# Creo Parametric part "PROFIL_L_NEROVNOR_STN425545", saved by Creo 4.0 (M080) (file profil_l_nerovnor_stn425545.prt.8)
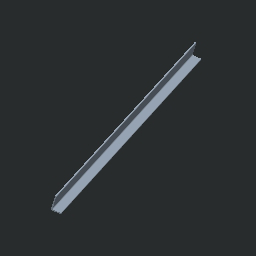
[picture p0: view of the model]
Units: millimeter Kilogram Sec (mmKs); MM, KILOGRAM, SECS
Materials in the file: OCEL_N

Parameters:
  MFG_WP_MATERIAL = "OCEL"
  NAZOV = "PROFIL_L_NEROVNOR_STN425545"
  NORMA = "STN 42 5545"
  PTC_MATERIAL_NAME = "OCEL_N"

Other parameters: HMOTNOST, HUSTOTA

Created from: L_NEROVNOR.PRT

Layers: 1, 2, 3, 4, 5, 6, 7, 8, 9, 10, 11, 12, 13, 14, 15, 16, 17, 18, 19, 20, 21, 22, 23, 24, 25, 26, 27, 28, 29, 30, 31, 32

Family table entries: GENERIC, PROFIL_L_45X30X4, PROFIL_L_NEROVNOR_STN425545, value(d_val), 2/>, value(i_val), PROFIL_L_50X30X4, PROFIL_L_NEROVNOR_STN425545, !/I, 2/>, PROFIL_L_60X40X5, PROFIL_L_NEROVNOR_STN425545, !/N, 2/D, PROFIL_L_75X50X6, PROFIL_L_NEROVNOR_STN425545, 2/I, PROFIL_L_80X60X6, PROFIL_L_NEROVNOR_STN425545, !/T, 2/N, 2/ , PROFIL_L_90X60X8, PROFIL_L_NEROVNOR_STN425545, 2/N, 2/ , 2/ , PROFIL_L_100X65X10, PROFIL_L_NEROVNOR_STN425545, !/Y, 2/$, 2/$, PROFIL_L_110X70X10, PROFIL_L_NEROVNOR_STN425545, 2/$, 2/$, PROFIL_L_120X80X10, PROFIL_L_NEROVNOR_STN425545, !/^, 2/T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

Surfaces: 8 plane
